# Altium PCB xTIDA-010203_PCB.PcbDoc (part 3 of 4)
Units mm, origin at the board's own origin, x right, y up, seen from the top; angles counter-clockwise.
Board outline 200 x 130 mm, 4 copper layers (Top Layer, Signal Layer 1, Signal Layer 2, Bottom Layer), stack 1.588 mm thick; 249 components, 140 nets, 768 pads, 520 vias.
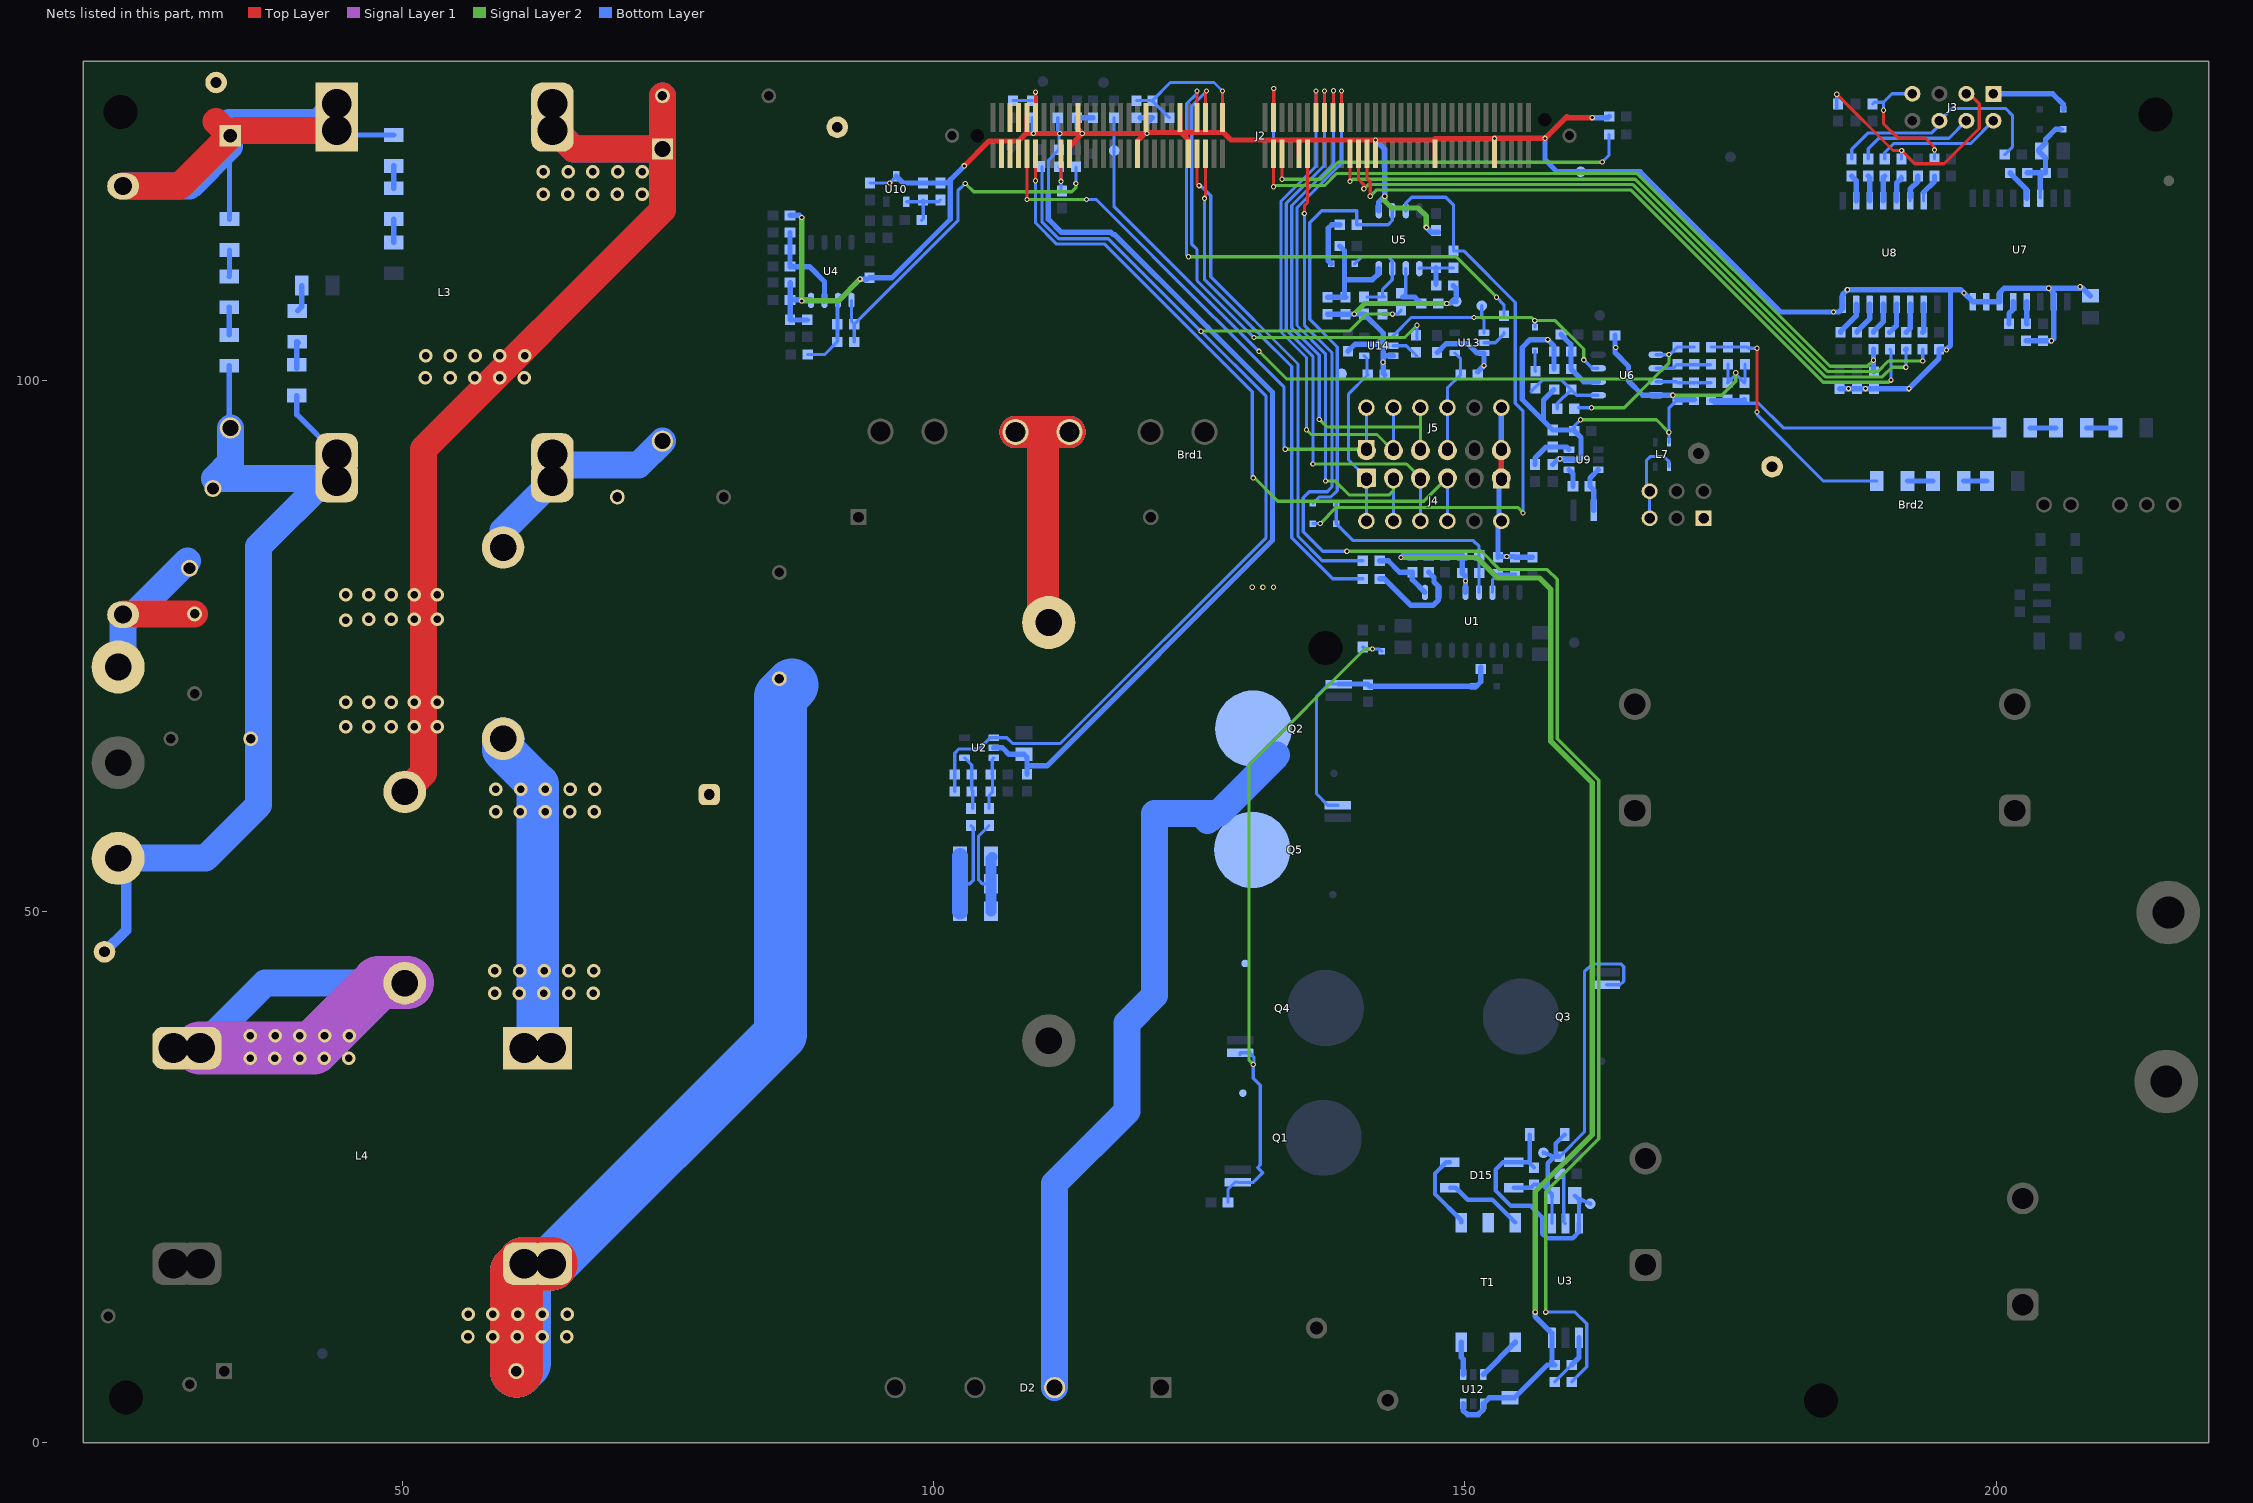
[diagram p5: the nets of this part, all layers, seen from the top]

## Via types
v1: diameter 0.5, hole 0.3, Top Layer to Bottom Layer, tented both sides, 429 vias
v2: diameter 1.27, hole 0.711, Top Layer to Bottom Layer, tented both sides, 90 vias
v3: diameter 0.5, hole 0.3, Top Layer to Bottom Layer, 1 vias

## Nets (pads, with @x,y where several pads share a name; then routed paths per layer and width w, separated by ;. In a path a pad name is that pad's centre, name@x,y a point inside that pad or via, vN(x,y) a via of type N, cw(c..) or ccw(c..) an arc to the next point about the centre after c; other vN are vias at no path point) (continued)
FSI-RX1-Sec: J3.7 R79.1 R83.2 | length 13
  Top Layer w0.3: v1(189.4,125.4) 189.4,124.139 190.79,122.749 193.351,122.749 194.2,121.9 v1(194.2,121.664)
  Bottom Layer w0.3: R83.2@188.375,125.98 188.535,126.14 189.4,126.14 ; v1(189.4,125.4) 189.4,126.14 ; J3.7@192.12,126.94 190.2,126.94 189.4,126.14 ; R79.1@194.188,120.8 194.188,121.288 194.2,121.3 v1(194.2,121.664)
FSI-RXCLK-Pri: J2.59 J2.60 R82.2 R90.2 | length 81.9
  Top Layer w0.3: v1(132,118.2) 132,118.7 J2.59@132,121.3 ; J2.60@132,124.7 132.027,124.727 v1(132.027,127.431)
  Signal Layer 2 w0.3: v1(132,118.2) 132.1,118.3 136.793,118.3 137.92,119.427 166.241,119.427 184.367,101.3 187.88,101.3 v1(188.453,101.874)
  Bottom Layer w0.3: v1(132,118.2) 132,127.404 v1(132.027,127.431)
  Bottom Layer w0.5: R82.2@188.453,102.901 v1(188.453,101.874) 188.453,100.847 R90.2@188.5,100.8
FSI-RXCLK-Sec: J3.3 R81.1 R85.2 | length 24
  Top Layer w0.3: v1(185,126.89) 190.29,121.6 v1(191.1,121.6) 192.336,120.364 195.086,120.364 198.4,123.678 198.4,126 197.46,126.94 J3.3@197.2,126.94
  Bottom Layer w0.3: R85.2@185,125.588 v1(185,126.89) ; R81.1@191.075,120.8 191.1,120.825 v1(191.1,121.6) ; J3.3@197.2,126.94 J3.3@197.2,127.4
FSI-TX0-Pri: J2.79 R103.2 | length 64.3
  Top Layer w0.3: J2.79@140,121.3 140,118.9 140.5,118.4 v1(140.5,118)
  Signal Layer 2 w0.3: v1(140.5,118) 140.9,118.4 165.833,118.4 183.934,100.298 185.643,100.298 185.644,100.3 186.556,100.3 186.557,100.298 187.243,100.298 187.244,100.3 188.156,100.3 188.157,100.298 189.298,100.298 190.2,101.2 v1(191.5,101.2)
  Bottom Layer w0.3: v1(191.5,101.2) R103.2@191.5,102.86
  Bottom Layer w0.5: R103.2@191.5,102.86 R103.2@191.54,102.901
FSI-TX0-Sec: J3.4 R100.1 | length 11.3
  Bottom Layer w0.3: R100.1@187.962,120.8 187.962,121.762 188.964,122.764 195.564,122.764 J3.4@197.2,124.4
FSI-TX1-Pri: J2.77 R102.2 | length 65.6
  Top Layer w0.3: v1(139.2,118.7) J2.77@139.2,121.3
  Signal Layer 2 w0.3: v1(139.2,118.7) 139.4,118.9 166.04,118.9 184.14,100.8 188.862,100.8 189.862,101.8 v1(193.083,101.8)
  Bottom Layer w0.3: v1(193.083,101.8) R102.2@193.083,102.901
FSI-TX1-Sec: J3.6 R35.2 R101.1 | length 22.1
  Bottom Layer w0.3: R101.1@186.405,120.8 186.405,121.705 187.964,123.264 193.952,123.264 194.66,123.972 J3.6@194.66,124.4 195.815,125.555 200.908,125.555 201.523,124.94 201.523,121.925 R35.2@200.815,121.217
FSI-TXCLK-Pri: J2.81 R104.2 | length 63.9
  Top Layer w0.3: J2.81@140.8,121.3 140.8,118.949 141.1,118.649 v1(141.1,117.3)
  Signal Layer 2 w0.3: v1(141.1,117.3) 141.7,117.9 165.626,117.9 183.727,99.798 185.85,99.798 185.851,99.8 186.349,99.8 186.35,99.798 187.45,99.798 187.451,99.8 187.949,99.8 187.95,99.798 189.506,99.798 189.507,99.8 189.9,99.8 v1(190.1,100)
  Bottom Layer w0.3: R104.2@189.997,102.901 190.1,102.797 v1(190.1,100)
FSI-TXCLK-Sec: J3.2 R99.1 | length 12.1
  Bottom Layer w0.3: R99.1@189.518,120.8 189.518,121.418 190.364,122.264 197.604,122.264 J3.2@199.74,124.4
GaN_FLT_H: Brd1.6 J2.74 J5.3 | length 53.6
  Top Layer w0.3: J2.74@137.6,124.7 137.639,124.739 v1(137.639,127.225)
  Signal Layer 2 w0.3: v1(136.3,96.3) 137,95.6 145.82,95.6 ; Brd1.6@145.82,93.346 J5.3@145.82,93.596 145.82,95.6 ; J5.3@145.82,97.156 145.82,95.6
  Bottom Layer w0.3: v1(136.3,96.3) 136.3,102.34 133.711,104.929 133.711,116.433 137.639,120.361 v1(137.639,127.225) ; J5.3@145.82,93.596 J5.3@145.82,97.406
GaN_FLT_L: Brd1.3 J2.76 J4.5 pad.4 | length 54.4
  Top Layer w0.3: J2.76@138.4,124.7 v1(138.4,127.2)
  Signal Layer 2 w0.3: v1(136.9,90.5) 137.8,90.5 139.1,89.2 142.9,89.2 143.28,89.58 J4.5@143.28,90.556 pad.4@143.28,90.806
  Bottom Layer w0.3: v1(136.9,90.5) 136.9,90.7 136.9,102.447 134.211,105.136 134.211,116.226 138.4,120.415 v1(138.4,127.2) ; J4.5@143.28,86.746 J4.5@143.28,90.556 pad.4@143.28,90.806
GaN_OC_H: Brd1.4 J2.70 J5.2 pad.3 | length 49.8
  Top Layer w0.3: J2.70@136,124.7 v1(136,127.2)
  Signal Layer 2 w0.3: v1(135.1,95.322) 135.537,94.885 141.741,94.885 pad.3@143.28,93.346
  Bottom Layer w0.3: v1(135.1,95.322) 135.1,102.126 132.7,104.526 132.7,116.836 136,120.136 v1(136,127.2) ; pad.3@143.28,93.346 J5.2@143.28,93.596 J5.2@143.28,97.406
GaN_OC_L: Brd1.5 J2.72 J4.4 | length 54.6
  Top Layer w0.3: J2.72@136.8,124.7 v1(136.8,127.2)
  Signal Layer 2 w0.3: v1(135.7,92.1) 140.793,92.1 140.8,92.107 144.519,92.107 Brd1.5@145.82,90.806
  Bottom Layer w0.3: v1(135.7,92.1) 135.7,102.233 133.2,104.733 133.2,116.629 136.8,120.229 v1(136.8,127.2) ; J4.4@145.82,86.746 J4.4@145.82,90.556
GND-c: Brd1.11 Brd1.12 C11.2 C13.2 C18.1 C20.2 C21.1 C22.1 C23.2 C24.1 C27.1 C28.2 C29.2 C31.2 C32.1 C34.1 C35.1 C36.2 C38.2 C39.2 C40.1 C41.2 C42.2 C43.1 C44.1 C45.1 C46.1 C47.1 C48.2 C49.1 C52.2 C53.2 C54.1 C57.2 C58.2 C59.2 C62.2 C63.2 C64.1 C65.2 C66.2 C67.2 C68.2 J2.7 J2.10 J2.19 J2.22 J2.35 J2.38 J2.46 J2.47 J2.65 J2.83 J2.97 J2.111 J4.1 J5.6 L4.4 L7.2 pad.1@78.9,61 pad.2@149.2,107.4 pad.2@160.9,119.6 pad.5 pad.6 R14.2 R16.2 R19.1 R20.1 R21.1 R30.2 R33.2 R37.1 R41.1 R44.1 R47.2 R54.2 R55.2 R62.1 R63.1 R65.2 R75.1 R77.1 R88.1 R89.1 R90.1 R92.1 R96.1 R97.1 TP5.1 TP6.1 U1.4 U2.2 U3.3 U4.4 U5.5 U6.4 U7.2 U7.6 U7.7 U7.8 U8.8 U9.2 U10.3 U12.4 U12.6 U13.3 U14.3 | length 683.5
  Top Layer w0.5: v1(102.9,120.16) 105.24,122.5 J2.7@108,122.5 ; J2.7@108,121.3 J2.7@108,122.5 ; J2.10@108.8,124.7 108.8,123.3 108.7,123.2 ; J2.19@112.8,121.3 112.8,122 v1(114,123.2) ; J2.22@113.6,124.7 113.6,123.6 J2.22@113.824,123.376 ; J2.35@119.2,121.3 119.2,122.5 v1@119.9,123.2 ; J2.38@120,124.7 v1@120,123.3 ; J2.46@123.2,124.9 123.2,123.3 ; J2.47@124,121.3 124,122.6 123.3,123.3 ; J2.65@134.4,121.3 J2.65@134.4,122.6 ; J2.83@141.6,121.3 v1(141.6,122.6) ; J2.97@147.1,122.6 v1(141.6,122.6) ; J2.97@147.2,121.3 J2.97@147.2,122.5 ; 147.2,122.7 152.752,122.7 v1(152.8,122.748) ; J2.111@152.8,121.3 v1(152.8,122.748) ; pad.6@153.44,90.806 pad.5@153.44,93.346 ; v1(162,124.7) 159.7,124.7 159.6,124.8 v1(157.548,122.748) v1(152.8,122.748) ; J2.7@108,122.5 108.7,123.2 ; 108.7,123.2 v1(109.4,123.2) v1(111.876,123.2) v1(114,123.2) ; v1(114,123.2) v1@119.9,123.2 ; v1@119.9,123.2 v1@120,123.3 ; v1@120,123.3 123.2,123.3 ; 123.2,123.3 123.3,123.3 ; 123.3,123.3 127.3,123.3 128,122.6 J2.65@134.4,122.6 ; J2.65@134.4,122.6 v1(141.6,122.6)
  Top Layer w5: C11.2@60.75,6.75 60.75,16.1 L4.4@61.5,16.85 L4.4@64,16.85
  Signal Layer 1 w5: C11.2@60.75,6.75 60.75,16.1 L4.4@61.5,16.85 L4.4@64,16.85
  Signal Layer 2 w0.3: v1(160.882,96.262) 168.038,96.262 v1(169.2,95.1) ; v1(169.577,98.572) 174.178,98.572 175.5,99.893 v1(175.5,100.7)
  Signal Layer 2 w0.5: v1(87.6,115.3) v1(87.6,107.455) 91.055,107.455 v1(93.1,109.5) ; v1(139.6,106.22) 140.58,107.2 v1(148.3,107.2) ; v1(142.46,117.3) 142.46,116.873 143.132,116.2 145.607,116.2 146.384,115.424 v1(146.384,114.372) ; v1(144,83.3) 151.164,83.3 153.093,81.371 157.029,81.371 158.1,80.3 158.1,66 162,62.1 162,29 156.622,23.622 v1(156.622,12.3)
  Signal Layer 2 w5: C11.2@60.75,6.75 60.75,16.1 L4.4@61.5,16.85 L4.4@64,16.85
  Bottom Layer w0.3: C59.2@94.047,118.545 v1(95.874,118.545) U10.3@96.505,119.176 ; R20.1@102.512,52.602 103.421,52.602 103.747,52.929 103.747,57.863 R30.2@103.526,58.084 ; C46.1@109.3,124.7 109.3,123.3 v1(109.4,123.2) ; 110.8,117.7 110.825,117.725 110.825,120.7 111.789,121.664 C47.1@111.8,121.664 v1@111.8,123.124 ; v1@111.7,123.224 C18.1@111.7,124.7 ; C58.2@160.304,95.229 160.304,95.684 v1(160.882,96.262) ; v1(169.2,95.1) 169.2,97.349 C43.1@170,98.149 ; L7.2@169.222,94.15 v1@169.222,94.887 ; C42.2@174.726,99.749 C42.2@174.774,99.797 ; C39.2@174.774,101.501 C42.2@174.774,99.797 ; R55.2@176.363,101.501 176.363,99.809 R63.1@176.303,99.749 175.515,100.537 C42.2@174.774,99.797
  Bottom Layer w0.5: R44.1@86.5,107.556 R44.1@86.515,107.556 ; C36.2@86.5,109.166 86.515,109.151 R44.1@86.515,107.556 ; C63.2@86.5,115.5 87.4,115.5 v1(87.6,115.3) ; R41.1@88.125,105.662 C31.2@86.515,105.662 R44.1@86.515,107.556 ; U4.4@88.475,107.556 R44.1@86.515,107.556 ; v1(93.1,109.5) C32.1@93.725,109.5 ; C32.1@94,109.625 96.076,109.625 101.583,115.132 101.583,118.843 ; U10.3@96.505,119.176 97.136,118.545 R96.1@99.034,118.545 R97.1@100.658,118.545 101.285,118.545 101.583,118.843 ; v1(102.9,120.16) 101.583,118.843 ; U2.2@105.675,65.4 106.5,65.4 107.116,64.784 C22.1@108.5,64.784 ; C22.1@108.7,64.6 108.8,64.5 108.8,63.7 ; C62.2@108.8,62.9 108.8,63.7 ; 110.8,117.7 110.8,115.149 112.049,113.9 116.712,113.9 116.912,113.7 117.054,113.7 125.453,105.301 125.462,105.301 125.872,104.891 125.872,104.881 131.9,98.854 131.9,84.932 110.668,63.7 108.8,63.7 ; v1(114,123.2) 113.5,123.7 C34.1@113.5,124.7 C44.1@115,124.7 ; C52.2@119.5,124.65 119.45,124.7 R77.1@120.6,124.7 120.1,124.2 v1(120.1,123.2) ; R65.2@137.086,106.209 139.051,106.209 139.062,106.22 v1(139.6,106.22) C45.1@140.522,106.22 142.322,104.42 142.322,104 ; C68.2@139,102.72 139.011,102.72 139.667,103.375 141.697,103.375 142.322,104 ; v1(141.6,122.6) 142.46,121.74 v1(142.46,117.3) 141.907,116.748 U5.5@141.907,115.938 ; R14.2@142.464,100.499 142.322,100.641 142.322,102.285 ; U14.3@143.272,102.285 142.322,102.285 ; v1(144,83.3) 144.22,83.52 C21.1@145.066,83.52 C20.2@146.606,83.52 C28.2@148.121,83.52 C24.1@149.747,83.52 R37.1@149.747,81.845 150.065,81.526 v3(150.065,81.1) U1.4@150.065,80.025 ; v1(146.384,114.372) 146.834,113.922 C35.1@147.486,113.922 ; C66.2@147.4,102.599 147.411,102.599 148.231,103.418 150.261,103.418 151.13,102.549 U13.3@151.8,102.549 v1(151.8,101.36) R16.2@151.2,100.76 ; C41.2@147.507,107.2 v1(148.3,107.2) 148.608,107.2 pad.2@148.808,107.4 ; R54.2@148.9,108.9 149.2,108.6 149.2,107.792 pad.2@148.808,107.4 ; pad.2@149.2,107.4 pad.2@148.808,107.4 ; U12.6@149.847,3.678 149.847,3.059 150.253,2.653 151.253,2.653 151.747,3.147 U12.4@151.747,3.678 152.306,4.237 C67.2@154.253,4.237 154.667,4.237 157.758,7.328 C27.1@158.453,7.328 158.196,7.585 U3.3@158.196,9.878 158.196,10.304 156.622,11.878 v1(156.622,12.3) ; J4.1@153.121,86.646 C23.2@153.121,83.336 153.194,83.409 v1(153.953,83.409) 154.664,83.409 R33.2@154.737,83.336 C29.2@156.371,83.336 ; J4.1@153.221,86.746 153.221,90.587 pad.6@153.44,90.806 ; pad.5@153.44,93.346 J5.6@153.44,93.596 J5.6@153.44,97.406 ; v1(157.548,122.748) 157.548,120.752 158.7,119.6 pad.2@160.9,119.6 166.5,119.6 179.7,106.4 v1(184.7,106.4) 185.2,106.4 185.555,106.755 U8.8@185.555,107.125 185.555,108.055 v1(186,108.5) 195.7,108.5 ; C57.2@158.27,92.062 158.808,92.6 v1(158.963,92.6) 159.26,92.6 159.348,92.512 U9.2@159.804,92.512 160.729,92.512 160.929,92.712 160.929,94.604 C58.2@160.304,95.229 160.233,95.3 R92.1@158.27,95.3 157.4,96.17 ; C38.2@158.4,99.11 157.4,98.11 157.4,96.17 ; C64.1@158.4,101.046 R47.2@158.4,102.7 158.4,103.206 v1(157.8,103.806) 156.14,103.806 155.4,103.067 155.4,98.17 157.4,96.17 ; v1(162,124.7) 163.48,124.7 C53.2@163.58,124.8 ; C40.1@164.129,104.212 164.129,102.579 165.4,101.307 165.4,99.911 166.739,98.572 U6.4@167.997,98.572 v1(169.577,98.572) C43.1@170,98.149 R62.1@171.575,98.149 ; R88.1@185.25,99.174 185.276,99.2 v1(186.1,99.2) v1(187.7,99.2) R90.1@188.5,99.2 v1(191.8,99.2) 194.625,102.025 C54.1@194.625,102.901 195.332,102.901 195.7,103.269 195.7,108.5 ; R75.1@202.8,103.701 v1(205.194,103.701) 205.425,103.931 U7.2@205.425,107.375 205.425,108.175 v1(204.95,108.65) ; C48.2@208.866,107.916 208.132,108.65 v1(204.95,108.65) ; 142.322,102.285 142.325,102.288 142.325,102.775 142.322,102.778 142.322,103.691 142.325,103.695 142.325,103.725 142.322,103.728 142.322,104 ; 195.7,108.5 196.68,108.5 v1(196.98,108.2) U7.8@197.805,107.375 U7.7@199.075,107.375 U7.6@200.345,107.375 200.345,108.234 200.761,108.65 v1(204.95,108.65)
  Bottom Layer w1.5: R19.1@102.512,50.004 R20.1@102.512,52.602 R21.1@102.512,55.2
  Bottom Layer w5: C11.2@60.75,6.75 61.5,7.5 L4.4@61.5,16.85 ; L4.4@64,16.85 85.6,38.45 85.6,70.2 86.7,71.3
  other v1: 130,80.5 131,80.5 132,80.5 142.297,101.685 195.318,102.837 164.2,103.067 207.9,108.78
  other v2: 56.2,10 58.525,10 60.85,10 63.175,10 65.5,10 56.225,12.109 58.55,12.109 60.875,12.109 63.2,12.109 65.525,12.109
GND-RLY: C6.2 C19.2 D15.2 D16.2 pad.2@157.4,27.3 Q3.2 R31.1 U3.4 | length 40.1
  Bottom Layer w0.3: U3.4@158.196,20.628 C19.2@158.196,23.128 ; R31.1@158.916,26.916 161.25,29.25 161.25,44.315 161.985,45.05 164.715,45.05 164.95,44.815 164.95,43.45 164.6,43.1 Q3.2@163.35,43.1
  Bottom Layer w0.4: D15.2@154.6,24 156.2,24 C6.2@156.5,24.3 157.274,24.3 C19.2@157.797,23.777 ; pad.2@157.4,27.3 R31.1@158.484,26.916 ; C19.2@158.196,23.128 158.196,23.378 C19.2@157.797,23.777 ; R31.1@158.919,26.916 R31.1@158.916,26.916 ; D16.2@159.396,29 158.563,28.167 158.563,27.27 R31.1@158.916,26.916 ; C19.2@157.797,23.777 157.797,25.403 157.8,25.4 157.8,26.3 158.416,26.916 R31.1@158.484,26.916 ; R31.1@158.484,26.916 R31.1@158.916,26.916
GND-s: Brd2.1
Iac: C26.1 R28.1 R36.1 R48.2 R66.2 U2.1 | length 108.7
  Signal Layer 2 w0.3: v1(125.172,104.601) 125.179,104.608 139.108,104.608 140.709,106.209 v1(143.2,106.209)
  Bottom Layer w0.3: R36.1@101.998,61.302 R36.1@101.996,61.302 C26.1@101.996,62.9 101.996,64.896 102.4,65.3 104.3,65.3 105.35,66.35 U2.1@105.675,66.35 106.909,66.35 107.459,65.8 111.919,65.8 131.3,85.181 131.3,98.464 125.172,104.591 v1(125.172,104.601) 125.163,104.601 116.464,113.3 111.8,113.3 110.2,114.9 R28.1@110.2,120.1 ; R66.2@142.261,106.209 v1(143.2,106.209) 143.634,106.209 R48.2@144,106.575
ISO_12V_RLY: C6.1 C19.1 D15.1 D16.1 pad.2@161.8,22.5 U3.6 | length 24.6
  Bottom Layer w0.4: D16.1@156.121,29 C6.1@156.121,26.279 ; C6.1@156.5,25.9 C6.1@156.121,26.279 ; C19.1@160.353,23.253 C19.1@160.506,23.1 ; U3.6@160.726,20.628 160.726,19.826 160.153,19.253 157.853,19.253 157.831,19.276 157.679,19.276 157.286,19.669 157.286,21.214 156.2,22.3 154.353,22.3 152.9,23.753 152.9,25.7 153.6,26.4 D15.1@154.6,26.4 156,26.4 C6.1@156.121,26.279 ; U3.6@160.736,20.628 160.736,22.87 C19.1@160.506,23.1 ; pad.2@161.8,22.5 C19.1@160.506,23.1
ISONC2: T1.5
LF-H-PROT: C21.2 R26.1 U1.1 | length 5.9
  Bottom Layer w0.5: R26.1@142,83 142.793,83 143.873,81.92 C21.2@145.066,81.92 145.066,81.214 U1.1@146.255,80.025
LF-L-PROT: C20.1 R29.1 U1.2 | length 9.8
  Bottom Layer w0.5: R29.1@142,81.3 142.438,81.3 144.938,78.8 147,78.8 147.525,79.325 U1.2@147.525,80.025 147.525,80.584 147.105,81.005 147.105,81.421 C20.1@146.606,81.92
LF-MOSH: J2.49 R26.2 | length 47.2
  Top Layer w0.3: J2.49@124.8,121.3 124.8,118.4 v1@125,118.2
  Bottom Layer w0.3: v1(125,118.3) 125.149,118.3 126.1,117.349 126.1,109.712 134.3,101.512 134.3,85.288 136.588,83 R26.2@140.4,83
LF-MOSL: J2.51 R29.2 | length 47.9
  Top Layer w0.3: v1(125.5,117.1) 125.6,117.2 125.6,118.7 J2.51@125.6,121.3
  Bottom Layer w0.3: v1(125.5,117.1) 125.5,109.488 130.38,104.608 130.404,104.608 130.756,104.256 130.756,104.232 133.709,101.278 133.709,93.751 133.711,93.749 133.711,93.249 133.709,93.247 133.709,85.172 137.581,81.3 R29.2@140.4,81.3
LFMOS_DIS: C24.2 D4.1 D5.1 R37.2 U1.5 | length 20.6
  Bottom Layer w0.3: D5.1@137.9,88.4 D4.1@137.9,86.5 139.5,84.9 150.8,84.9 151.347,84.353 C24.2@151.347,83.52 R37.2@151.347,81.845 151.347,80.037 U1.5@151.335,80.025
NetBrd2_5: Brd2.5 Brd2.6 L7.3 | length 8.5
  Bottom Layer w0.3: Brd2.5@167.391,87 Brd2.6@167.391,89.54 167.1,89.831 167.1,92.45 167.45,92.8 168.745,92.8 169.222,92.323 L7.3@169.222,91.85
NetC7_1: C7.1 F1.2 pad.1@23.283,73 RV1.2 | length 21.3
  Top Layer w2.54: F1.2@23.75,77.93 23.82,78 C7.1@30.476,78
  Bottom Layer w2.54: pad.1@23.283,72.073 pad.1@23.75,72.54 ; pad.1@23.96,72.75 pad.1@23.75,72.54 ; RV1.2@29.8,83 24.73,77.93 F1.2@23.75,77.93 pad.1@23.75,72.54
NetC8_1: C8.1 C12.1 L2.1 L3.4 | length 107.4
  Top Layer w2.54: L2.1@50.25,61.25 52,63 52,93.5 74.5,116 C12.1@74.5,121.75 ; L3.4@64.15,126 64.15,123.75 66.15,121.75 C12.1@74.5,121.75 ; C8.1@74.5,126.75 C12.1@74.5,121.75
  Bottom Layer w2.54: L3.4@64.15,126 64.15,123.75 66.15,121.75 C12.1@74.5,121.75 C8.1@74.5,126.75
  other v2: 44.7,67.4 46.85,67.4 49,67.4 51.15,67.4 53.3,67.4 44.7,69.7 46.85,69.7 49,69.7 51.15,69.7 53.3,69.7 44.7,77.4 46.85,77.5 49,77.5 51.15,77.5 53.3,77.5 44.7,79.8 46.85,79.8 49,79.8 51.15,79.8 53.3,79.8 52.2,100.2 54.525,100.2 56.85,100.2 59.175,100.2 61.5,100.2 52.225,102.309 54.55,102.309 56.875,102.309 59.2,102.309 61.525,102.309 63.275,117.491 65.6,117.491 67.925,117.491 70.25,117.491 72.575,117.491 63.3,119.6 65.625,119.6 67.95,119.6 70.275,119.6 72.6,119.6
NetC10_1: C10.1 F1.1 L3.1 R9.1 R15.2 TP3.1 | length 63.7
  Top Layer w2.54: F1.1@23.75,118.25 29.084,118.25 C10.1@33.834,123 ; 32.5,124.334 C10.1@33.834,123 ; L3.1@43.85,123.5 34.334,123.5 C10.1@33.834,123
  Bottom Layer w0.5: 33.75,121.983 33.752,121.981 R15.2@33.752,115.15 ; L3.1@43.85,123.5 44.29,123.06 R9.1@49.2,123.06
  Bottom Layer w2.54: F1.1@23.75,118.25 30.017,118.25 33.75,121.983 33.75,124.25 42.1,124.25 L3.1@43.85,126 L3.1@43.85,123.5
NetC10_2: C10.2 C14.2 L3.2 pad.1@23.283,55 R18.1 R22.1 RV1.1 TP4.1 | length 89
  Bottom Layer w0.5: R18.1@33.75,101.35 33.75,95.583 C10.2@33.834,95.5 ; R22.1@40.1,98.55 40.1,96.75 L3.2@43.8,93.05
  Bottom Layer w1: TP4.1@22,46.2 24.033,48.233 pad.1@24.033,55.018 ; L3.2@43.8,93.05 L3.2@43.85,93
  Bottom Layer w2.54: pad.1@24.033,55.018 31.518,55.018 36.5,60 36.5,84.35 42.9,90.75 32.35,90.75 33.834,92.234 C10.2@33.834,95.5 ; L3.2@43.85,90.5 L3.2@43.85,93
NetC12_2: C12.2 C15.2 L3.3 L5.1 | length 22
  Bottom Layer w2.54: L5.1@59.5,84.25 59.5,85.85 L3.3@64.15,90.5 64.15,92.75 64.9,92 72.25,92 C12.2@74.5,94.25
NetC16_2: C16.2 R25.1 R27.1 U2.3 | length 5
  Bottom Layer w0.3: R27.1@105.226,59.684 105.226,60.897 105.549,61.22 105.549,62.881 105.526,62.881 105.526,64.301 U2.3@105.675,64.45
NetC23_1: C23.1 R33.1 U1.6 | length 3.5
  Bottom Layer w0.3: U1.6@152.605,80.025 152.605,81.22 C23.1@153.121,81.736 R33.1@154.737,81.736
NetC26_2: C26.2 R30.1 R36.2 U2.4 | length 5.1
  Bottom Layer w0.3: U2.4@102.925,64.45 103.596,63.779 103.596,61.467 103.696,61.367 R30.1@103.696,59.702
NetC27_2: C27.2 R105.1 U3.1 | length 5.1
  Bottom Layer w0.3: R105.1@158.45,5.728 158.453,5.728 C27.2@160.053,7.328
  Bottom Layer w0.5: C27.2@160.053,7.328 160.736,8.011 U3.1@160.736,9.878
NetC30_1: C30.1 R39.2 R40.2 U4.2 | length 11.1
  Bottom Layer w0.3: R39.2@88.164,102.4 89.75,102.4 R40.2@90.95,103.6 ; R40.2@90.95,103.6 C30.1@90.95,105.251 90.95,107.435 U4.2@91.015,107.5 91.015,103.665 R40.2@90.95,103.6
NetC30_2: C30.2 R40.1 R42.2 U4.1 | length 34.4
  Signal Layer 2 w0.3: v1(103,118.5) 103.775,117.725 113.025,117.725 113.4,118.1 v1(113.4,118.5)
  Bottom Layer w0.3: U4.1@92.285,107.5 92.285,105.516 C30.2@92.55,105.251 ; R40.1@92.55,103.6 C30.2@92.55,105.251 ; v1(103,118.5) 102.3,117.8 102.3,115.001 C30.2@92.55,105.251 ; v1(113.4,118.5) R42.2@113.4,120.064
NetC33_1: C33.1 R43.2 R45.1 U4.3 | length 8.9
  Bottom Layer w0.5: C33.1@86.5,113.89 R45.1@86.5,112.283 86.5,111.479 R43.2@86.5,110.674 88.326,110.674 89.745,109.255 U4.3@89.745,107.5 U4.3@89.7,107.455
NetC37_1: C37.1 R52.1 R53.1 U6.2 | length 5.3
  Bottom Layer w0.3: U6.2@167.997,101.112 169.611,101.112 169.935,101.436 R52.1@173.118,101.436
NetC38_1: C38.1 R49.1 R57.2 U6.5 | length 9.7
  Bottom Layer w0.3: R57.2@156.249,98.949 157.336,100.036 159.074,100.036 C38.1@160,99.11 ; R49.1@158.7,97.3 158.7,97.81 C38.1@160,99.11 ; C38.1@159.976,99.11 C38.1@159.988,99.098 ; U6.5@162.547,98.572 160.538,98.572 C38.1@160,99.11
NetC41_1: C41.1 R48.1 U5.2 | length 4.5
  Bottom Layer w0.3: R48.1@144.136,107.82 144.447,108.131 U5.2@144.447,110.488
  Bottom Layer w0.5: R48.1@144.136,107.82 145.255,107.82 C41.1@145.7,107.375
NetC43_2: C43.2 R61.2 R62.2 U6.3 | length 5.2
  Bottom Layer w0.3: U6.3@167.997,99.842 169.907,99.842 C43.2@170,99.749 R62.2@171.575,99.749 R61.2@173.151,99.749
NetC45_2: C45.2 D10.1 R66.1 U5.3 | length 9.5
  Bottom Layer w0.3: D10.1@139.626,110.948 140.299,111.622 142.786,111.622 143.177,111.23 U5.3@143.177,110.488 143.177,109.449 142.261,108.532 142.261,108.008 142.46,107.809 R66.1@142.261,107.809 140.824,107.809 C45.2@140.812,107.82
NetC46_2: C46.2 J2.12 R69.1 | length 5
  Top Layer w0.3: J2.12@109.6,124.7 v1(109.6,127.1)
  Bottom Layer w0.3: R69.1@107.5,126.3 C46.2@109.3,126.3 ; C46.2@109.6,126.29 v1(109.6,127.1)
NetC47_2: C47.2 J2.17 R70.2 | length 5
  Top Layer w0.3: v1(112,118.7) J2.17@112,121.3
  Bottom Layer w0.3: C47.2@111.8,120.064 112,119.864 v1(112,118.7) 112,117.896 R70.2@112.1,117.796
NetC50_1: C50.1 C51.2 D9.2 R71.1 U7.14 | length 9.9
  Bottom Layer w0.3: U7.14@204.155,117.125 204.155,117.99 ; D9.2@206.035,123.601 D9.2@206.3,123.601
  Bottom Layer w0.5: R71.1@202.935,119.5 204.1,119.5 ; 204.155,117.99 204.155,119.445 204.1,119.5 ; D9.2@206.035,123.601 205.601,123.601 204.65,122.65 204.65,122.301 203.984,121.635 203.984,121.55 204.65,120.884 C50.1@204.65,119.5 204.1,119.5
NetC52_1: C52.1 J2.56 R72.1 R77.2 | length 13.9
  Top Layer w0.3: J2.56@127.2,124.7 v1(127.2,127.2)
  Bottom Layer w0.3: C52.1@119.1,126.3 R77.2@120.6,126.3 ; R72.1@122.2,124.7 R77.2@120.6,126.3 ; v1(127.2,127.2) 126.4,128 122.3,128 R77.2@120.6,126.3
NetC56_1: C56.1 L6.1 U9.6 | length 4.3
  Bottom Layer w0.5: L6.1@162.129,87.762 162.129,89.662 C56.1@161.779,90.012 161.779,90.787 U9.6@162.554,91.562
NetC56_2: C56.2 U9.1 | length 1.7
  Bottom Layer w0.5: U9.1@159.804,91.562 160.179,91.187 C56.2@160.179,90.012
NetC64_2: C64.2 R46.1 R47.1 U6.6 | length 7.1
  Bottom Layer w0.5: R46.1@159.05,104.3 159.05,104.289 159.964,103.375 160,103.375 R47.1@160,102.7 C64.2@160,101.046 161.204,99.842 U6.6@162.547,99.842 ; R47.1@159.976,102.29 R47.1@159.976,102.7
NetC65_1: C65.1 R64.1 R65.1 U5.4 | length 10.6
  Bottom Layer w0.5: R65.1@137.086,107.809 137.096,107.798 C65.1@138.786,107.798 ; R64.1@138.236,112.622 138.686,112.172 138.686,109.449 ; C65.1@138.786,107.82 138.686,107.92 138.686,109.449 ; U5.4@141.907,110.488 141.907,110.044 141.312,109.449 138.686,109.449
NetD1_2: D1.2 Q1.1 Q4.1 R2.2 R4.2 | length 64.8
  Signal Layer 2 w0.3: v1(130.1,35.6) 129.7,36 129.7,63.799 140.601,74.7 v1(141.3,74.7)
  Bottom Layer w0.3: R2.2@127.713,22.6 127.713,23.853 128.4,24.54 128.61,24.54 Q1.1@128.65,24.5 130.1,24.5 131,25.4 130.501,25.899 130.75,26.148 130.75,33.652 130.1,34.302 v1(130.1,35.6) 130.157,35.657 130.157,36.299 129.756,36.7 Q4.1@128.85,36.7 Q4.1@128.85,36.5 ; R4.2@140.4,74.89 140.59,74.7 v1(141.3,74.7) 141.974,74.7 D1.2@142.197,74.477
NetD2_2: D2.2 Q1.3-4-5-6-7-8 Q2.9 Q4.3-4-5-6-7-8 Q5.9 R19.2 R20.2 R21.2 R27.2 | length 84.5
  Bottom Layer w0.3: R27.2@105.226,58.084 104.247,57.104 104.247,52.957 104.602,52.602 R20.2@105.412,52.602
  Bottom Layer w1: R19.2@105.412,50.004 R20.2@105.412,52.602 ; R20.2@105.412,52.779 105.412,54.969 R21.2@105.547,55.104
  Bottom Layer w2.54: D2.2@111.4,5.2 111.4,24.4 118.2,31.2 118.2,39.481 120.8,42.081 120.8,46.9 120.8,59.236 126.5,59.236 ; 125.8,58.536 126.5,59.236 ; Q2.9@132.3,64.7 126.836,59.236 126.5,59.236
NetD3_2: D3.2 Q2.1 Q5.1 R12.2 R13.2 | length 29.2
  Bottom Layer w0.3: Q5.1@138.05,60 137.1,60 136.05,61.05 136.05,70.25 137.2,71.4 Q2.1@138.15,71.4
  Bottom Layer w0.5: Q2.1@138.15,71.4 140.848,71.4 R12.2@140.9,71.348 141.048,71.2 D3.2@150.8,71.2 151.086,71.2 151.5,71.614 R13.2@151.5,72.8 R13.2@151.5,73
NetD6_1: D6.1 R57.1 | length 2
  Bottom Layer w0.3: D6.1@156.608,102.789 156.608,100.875 R57.1@156.647,100.836
NetD7_2: D7.2 J3.1 | length 7.4
  Bottom Layer w0.5: J3.1@199.74,126.94 205.322,126.94 206.3,125.962 D7.2@206.3,125.5
NetD10_2: D10.2 R68.1 | length 4.7
  Bottom Layer w0.5: D10.2@137.426,110.948 137.139,111.235 137.139,114.283 137.478,114.622 R68.1@138.231,114.622
NetD15_3: D15.3 T1.6 | length 7.5
  Bottom Layer w0.4: D15.3@148.6,24 149.147,24 150.276,22.87 152.59,22.87 T1.6@154.74,20.72
NetD15_4: D15.4 T1.4 | length 7.5
  Bottom Layer w0.4: D15.4@148.6,26.4 148.26,26.4 147.2,25.34 147.2,23.4 149.66,20.94 T1.4@149.66,20.72
NetJ2_50: J2.50 R74.2 | length 51
  Top Layer w0.3: J2.50@124.8,124.7 v1(124.8,127.2)
  Signal Layer 2 w0.3: v1(124,111.6) 149.186,111.6 v1(152.987,107.798)
  Bottom Layer w0.3: v1(124,111.6) 123.8,111.8 123.8,125.98 v1@124.82,127 ; v1(152.987,107.798) 153.678,107.107 R74.2@153.678,106.068
NetJ2_52: J2.52 R76.2 | length 45.9
  Top Layer w0.3: J2.52@125.6,124.7 125.6,127.1 v1(125.7,127.2)
  Signal Layer 2 w0.3: v1(130.156,104.008) 144.355,104.008 v1(145.5,105.152)
  Bottom Layer w0.3: v1(125.7,127.2) 125.32,126.82 125.32,126.793 124.3,125.773 124.3,112.8 124.8,112.3 124.8,109.363 v1(130.156,104.008) ; R76.2@145.5,103.841 v1(145.5,105.152)
NetJ2_61: J2.61 R78.2 | length 36
  Top Layer w0.3: v1(132.8,118.9) J2.61@132.8,121.3
  Signal Layer 2 w0.3: v1(132.8,118.9) 136.469,118.9 138.069,120.5 162.9,120.5 v1(162.925,120.525)
  Bottom Layer w0.3: v1(162.925,120.525) 163.58,121.18 R78.2@163.58,123.1
NetL2_2: L2.2 L4.2 | length 48.8
  Signal Layer 1 w2.54: L4.2@28.5,37.15 L4.2@31,37.15
  Signal Layer 1 w5: L4.2@31,37.15 41.65,37.15 47.8,43.3 L2.2@50.5,43.3
  Bottom Layer w2.54: L4.2@28.5,37.15 L4.2@31,37.15 37.1,43.25 L2.2@50.25,43.25
  other v2: 35.7,36.2 38.025,36.2 40.35,36.2 42.675,36.2 45,36.2 35.725,38.309 38.05,38.309 40.375,38.309 42.7,38.309 45.025,38.309
NetL4_1: L4.1 L5.2 | length 31
  Bottom Layer w2.54: L4.1@62.75,38.4 L4.1@64,37.15
  Bottom Layer w4: L5.2@59.5,66.25 59.5,65.2 62.75,61.95 L4.1@62.75,38.4
  other v2: 58.7,42.3 61.025,42.3 63.35,42.3 65.675,42.3 68,42.3 58.725,44.409 61.05,44.409 63.375,44.409 65.7,44.409 68.025,44.409 58.8,59.4 61.125,59.4 63.45,59.4 65.775,59.4 68.1,59.4 58.825,61.509 61.15,61.509 63.475,61.509 65.8,61.509 68.125,61.509
NetR1_1: R1.1 R5.2 | length 2.7
  Bottom Layer w0.5: R5.2@208.531,95.5 R1.1@211.222,95.5
NetR3_1: R3.1 R6.2 | length 2.2
  Bottom Layer w0.5: R6.2@196.95,90.5 R3.1@199.13,90.5
NetR5_1: R5.1 R7.2 | length 2.4
  Bottom Layer w0.5: R7.2@203.2,95.5 R5.1@205.631,95.5
NetR6_1: R6.1 R8.2 | length 2.4
  Bottom Layer w0.5: R8.2@191.67,90.5 R6.1@194.05,90.5
NetR9_2: R9.2 R10.1 | length 2.1
  Bottom Layer w0.5: R10.1@49.2,118.05 R9.2@49.2,120.16
NetR10_2: R10.2 R11.1 | length 2.2
  Bottom Layer w0.5: R11.1@49.2,112.95 R10.2@49.2,115.15
NetR15_1: R15.1 R17.2 | length 2.5
  Bottom Layer w0.5: R17.2@33.75,109.75 33.752,109.752 R15.1@33.752,112.25
NetR17_1: R17.1 R18.2 | length 2.6
  Bottom Layer w0.5: R18.2@33.75,104.25 R17.1@33.75,106.85
NetR22_2: R22.2 R23.1 | length 2.6
  Bottom Layer w0.5: R22.2@40.1,101.112 R23.1@40.1,103.612 ; R23.1@40.15,103.6 R23.1@40.25,103.5
NetR23_2: R23.2 R24.1 | length 2.6
  Bottom Layer w0.5: R23.2@40.15,106.5 40.55,106.9 R24.1@40.55,108.9
NetR32_1: R32.1 U3.5 | length 4.8
  Bottom Layer w0.3: R32.1@159.253,25.316 159.306,25.263 159.306,20.788 U3.5@159.466,20.628
NetR50_2: R50.2 R54.1 R58.1 U5.1 | length 4.8
  Bottom Layer w0.3: U5.1@145.717,110.488 145.788,110.559 147.286,110.559 R58.1@148.949,110.559
  Bottom Layer w0.5: R54.1@147.286,109 147.286,110.559 R50.2@147.286,110.572
NetR71_2: R71.2 U7.13 | length 3
  Bottom Layer w0.5: R71.2@201.335,119.5 201.335,119.445 202.885,117.895 U7.13@202.885,117.125
NetR73_1: R73.1 U7.5 | length 2.2
  Bottom Layer w0.5: R73.1@201.2,105.301 201.2,106.265 201.615,106.68 U7.5@201.615,107.375
NetR75_2: R75.2 U7.4 | length 2.1
  Bottom Layer w0.5: R75.2@202.885,105.301 202.885,105.458 U7.4@202.885,107.375
NetR79_2: R79.2 U8.15 | length 2.7
  Bottom Layer w0.3: U8.15@193.175,116.875 U8.15@193.175,117.675
  Bottom Layer w0.5: U8.15@193.175,117.675 194.188,118.688 R79.2@194.188,119.2
NetR80_2: R80.2 U8.14 | length 2.6
  Bottom Layer w0.3: U8.14@191.905,116.875 U8.14@191.905,117.2
  Bottom Layer w0.5: U8.14@191.905,117.2 191.905,117.974 192.632,118.701 R80.2@192.632,119.2
NetR81_2: R81.2 U8.13 | length 2.5
  Bottom Layer w0.3: R81.2@191.075,118.984 R81.2@191.075,119.2
  Bottom Layer w0.5: U8.13@190.635,116.875 190.635,118.544 R81.2@191.075,118.984
NetR82_1: R82.1 U8.5 | length 3
  Bottom Layer w0.5: R82.1@188.453,104.501 188.453,104.569 189.365,105.48 U8.5@189.365,107.125
NetR86_1: R86.1 U8.6 | length 3.1
  Bottom Layer w0.5: R86.1@186.91,104.501 186.91,104.569 188.095,105.754 U8.6@188.095,107.125
NetR87_1: R87.1 U8.7 | length 3.2
  Bottom Layer w0.5: R87.1@185.367,104.501 185.367,104.569 186.825,106.027 U8.7@186.825,107.125
NetR91_1: R91.1 R92.2 U9.3 | length 4.3
  Bottom Layer w0.5: R91.1@156.608,92.062 156.608,92.667 157.641,93.7 R92.2@158.27,93.7 159.566,93.7 U9.3@159.804,93.462
NetR94_1: R94.1 R96.2 R97.2 U10.1 | length 5.2
  Bottom Layer w0.3: U10.1@97.455,116.776 R96.2@99.034,116.776 ; R94.1@98.9,115.047 99.034,115.181 R96.2@99.034,116.776 ; R96.2@99.034,116.945 R96.2@99.034,116.776 ; R97.2@100.658,116.945 100.489,116.776 R96.2@99.034,116.776
NetR99_2: R99.2 U8.12 | length 2.4
  Bottom Layer w0.5: U8.12@189.365,116.875 189.365,119.047 R99.2@189.518,119.2
NetR100_2: R100.2 U8.11 | length 2.4
  Bottom Layer w0.5: R100.2@187.962,119.2 188.095,119.067 U8.11@188.095,116.875
NetR101_2: R101.2 U8.10 | length 2.5
  Bottom Layer w0.5: R101.2@186.405,119.2 186.825,118.78 U8.10@186.825,116.875
NetR102_1: R102.1 U8.2 | length 2.7
  Bottom Layer w0.5: R102.1@193.083,104.501 193.175,104.592 U8.2@193.175,107.125
NetR103_1: R103.1 U8.3 | length 2.8
  Bottom Layer w0.5: R103.1@191.54,104.501 191.905,104.865 U8.3@191.905,107.125
NetR104_1: R104.1 U8.4 | length 2.9
  Bottom Layer w0.5: R104.1@189.997,104.501 190.615,105.119 190.615,107.105 U8.4@190.635,107.125
NetT1_1: T1.1 U12.3 | length 4.3
  Bottom Layer w0.5: U12.3@151.747,6.428 154.74,9.421 T1.1@154.74,9.48
NetT1_3: T1.3 U12.1 | length 3.1
  Bottom Layer w0.5: T1.3@149.66,9.48 149.66,8.04 149.847,7.853 U12.1@149.847,6.428
OCP-N: D4.2 R58.2 U5.7 | length 58.6
  Signal Layer 2 w0.3: v1(136.4,86.5) 137.921,88.021 154.963,88.021 v1(155.484,87.5)
  Bottom Layer w0.3: D4.2@135.7,86.5 v1(136.4,86.5) ; U5.7@144.447,115.938 144.447,116.647 145,117.2 148.2,117.2 148.949,116.451 R58.2@148.949,112.159 149.881,112.159 154.74,107.3 154.74,97.83 155.484,97.086 v1(155.484,87.5)
OCP-P: D5.2 pad.2@138.4,100.6 R68.2 U5.6 | length 39.7
  Bottom Layer w0.3: D5.2@135.7,88.4 136.3,89 137.4,89 138,89.6 138,103.117 135.4,105.717 135.4,114.799 136.539,115.938 139.831,115.938 R68.2@139.831,114.622 142.786,114.622 143.177,115.013 U5.6@143.177,115.938
OVP: D6.2 pad.2@151.6,107 U6.7 U13.1 U14.1 | length 26.3
  Signal Layer 2 w0.3: v1(150.865,105.899) 156.272,105.899 v1(156.573,105.597) 158.528,105.597 161.2,102.925 v1(161.2,101.9)
  Bottom Layer w0.3: U14.1@143.272,104.185 144.986,105.899 v1(150.865,105.899) 151.6,105.899 ; pad.2@151.6,107 151.6,105.899 ; U13.1@151.8,104.449 151.8,105.699 151.6,105.899 ; D6.2@156.608,104.989 v1@156.608,105.355 ; v1(161.2,101.9) 161.988,101.112 U6.7@162.547,101.112
PFCG_1H: R74.1 U13.2 | length 2.4
  Bottom Layer w0.3: U13.2@151.8,103.499 151.821,103.52 152.874,103.52 153.678,104.325 R74.1@153.678,104.468
PFCG_1H_5V: Brd1.8 J5.4 R16.1 U13.4 | length 9.9
  Bottom Layer w0.3: Brd1.8@148.36,93.346 J5.4@148.36,93.596 J5.4@148.36,97.406 148.36,99.259 R16.1@149.6,100.499 149.6,101.999 U13.4@149.05,102.549
PFCG_1L: R76.1 U14.2 | length 2.6
  Bottom Layer w0.3: U14.2@143.272,103.235 144.506,103.235 R76.1@145.5,102.241
PFCG_1L_5V: Brd1.1 J4.6 pad.1@140.74,90.806 R14.1 U14.4 | length 17.2
  Bottom Layer w0.3: U14.4@140.522,102.285 140.8,102.007 R14.1@140.8,100.435 ; J4.6@140.74,86.746 J4.6@140.74,90.556 pad.1@140.74,90.806 139.062,92.484 139.062,98.697 R14.1@140.8,100.435 ; R14.1@140.864,100.499 R14.1@140.8,100.435
RELAY_CTRL: J2.67 R105.2 | length 147.6
  Top Layer w0.3: v1(134.9,115.672) 134.9,116.389 135.2,116.688 J2.67@135.2,121.3
  Signal Layer 2 w0.3: v1(138.9,83.9) 151.57,83.9 153.3,82.17 157.774,82.17 158.7,81.245 158.7,66.249 162.6,62.349 162.6,28.6 157.622,23.622 v1(157.622,12.3)
  Bottom Layer w0.3: v1(134.9,115.672) 134.9,105.171 137.5,102.571 137.5,89.95 137.05,89.5 135.36,89.5 134.8,88.94 134.8,85.725 136.625,83.9 v1(138.9,83.9) ; v1(157.622,12.3) 160.366,12.3 161.466,11.2 161.466,7.144 R105.2@160.05,5.728
Sense_B+: C42.1 R7.1 R61.1 R63.2 | length 31.4
  Bottom Layer w0.3: R61.1@173.151,98.149 173.214,98.085 173.471,97.829 177.631,97.829 179.96,95.5 R7.1@200.3,95.5
  Bottom Layer w0.5: R61.1@173.214,98.085 176.303,98.085 R63.2@176.303,98.149
Sense_B-: C39.1 R8.1 R52.2 R55.1 | length 24.5
  Top Layer w0.3: v1(177.5,97) v1(177.5,103)
  Bottom Layer w0.3: R52.2@173.183,103.101 C39.1@174.774,103.101 176.598,103.101 176.699,103 v1(177.5,103) ; v1(177.5,97) 177.5,96.75 183.75,90.5 R8.1@188.77,90.5
SWNODE1: Brd1.22 Brd1.23 L1.1 TP10.1 TP11.1 | length 93
  Top Layer w3: TP10.1@107.72,95.124 111.124,95.124 ; L1.1@110.645,77.395 110.3,77.74 110.3,94.3 111.124,95.124 ; TP11.1@112.8,95.124 111.124,95.124
  Signal Layer 1 w3: TP10.1@107.72,95.124 110.3,95.124 ; L1.1@110.85,77.19 110.3,77.74 110.3,95.124 ; TP11.1@112.8,95.124 110.3,95.124
  Signal Layer 2 w3: TP10.1@107.72,95.124 110.3,95.124 ; L1.1@110.85,77.19 110.3,77.74 110.3,95.124 ; TP11.1@112.8,95.124 110.3,95.124
  Bottom Layer w3: TP10.1@107.75,95.094 TP10.1@107.72,95.124 110.724,95.124 ; L1.1@110.575,77.325 110.3,77.6 110.3,94.7 110.724,95.124 ; TP11.1@112.8,95.124 110.724,95.124
TCK: J2.5
TDI: J2.8
TDO: J2.6
TEMP_H: Brd1.2 J2.9 J5.1 pad.2@140.74,93.346 | length 53.6
  Top Layer w0.3: v1(108.8,117) 108.8,116.9 J2.9@108.8,121.3
  Signal Layer 2 w0.3: v1(108.8,117) 108.892,117 108.896,116.996 v1(114.4,116.996) ; v1(133.111,93.5) 140.586,93.5 pad.2@140.74,93.346
  Bottom Layer w0.3: v1(114.4,116.996) 115.313,116.996 125.908,106.401 125.918,106.401 126.972,105.346 126.972,105.337 133,99.309 133,93.611 v1(133.111,93.5) ; pad.2@140.74,93.346 J5.1@140.74,93.596 J5.1@140.74,97.406
TEMP_L: Brd1.7 J2.11 J4.3 | length 65.8
  Top Layer w0.3: v1(109.6,118.75) J2.11@109.6,121.3
  Signal Layer 2 w0.3: v1(130.1,90.8) 130.206,90.8 132.406,88.6 146.154,88.6 Brd1.7@148.36,90.806
  Bottom Layer w0.3: v1(109.6,118.75) 109.6,114.793 111.593,112.8 116.115,112.8 130,98.915 130,91.006 130.1,90.906 v1(130.1,90.8) ; J4.3@148.36,86.746 J4.3@148.36,90.556 Brd1.7@148.36,90.806
TMS: J2.3
Vdc: C37.2 pad.2@117,121.6 R49.2 R53.2 R60.2 U6.1 | length 80.7
  Signal Layer 2 w0.3: v1(130.636,102.701) 133.237,100.1 167.7,100.1 ; v1(161.926,97.4) 165,97.4 167.7,100.1 ; v1(169.2,102.4) 169.2,101.6 167.7,100.1
  Bottom Layer w0.3: R60.2@117,124.7 pad.2@117,121.6 117,116.315 130.614,102.701 v1(130.636,102.701) ; R49.2@160.7,97.4 v1(161.926,97.4) ; U6.1@167.997,102.382 169.281,102.382 C37.2@170,103.101 R53.2@171.591,103.101
pads on no net: Brd2.8 FID1.1 FID2.1 FID3.1 H1.1 H2.1 H5.0 H6.0 H9.1 H10.1 H11.1 H12.0 H13.0 J2.1 J2.2 J2.4 J2.13 J2.14 J2.15 J2.16 J2.21 J2.23 J2.25 J2.26 J2.27 J2.28 J2.29 J2.30 J2.31 J2.32 J2.33 J2.34 J2.36 J2.37 J2.39 J2.40 J2.41 J2.42 J2.43 J2.44 J2.45 J2.53 J2.54 J2.55 J2.57 J2.58 J2.62 J2.63 J2.64 J2.66 J2.69 J2.71 J2.73 J2.75 J2.78 J2.80 J2.85 J2.86 J2.87 J2.88 J2.89 J2.90 J2.91 J2.92 J2.93 J2.94 J2.95 J2.96 J2.99 J2.100 J2.101 J2.102 J2.103 J2.104 J2.105 J2.106 J2.107 J2.108 J2.109 J2.110 J2.113 J2.114 J2.115 J2.116 J2.117 J2.118 J2.119 J2.120 J2.181 J2.182 J2.185 J2.186 LBL1.0 U1.7 U1.12 U1.13 U3.2 U4.5 U4.6 U4.7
